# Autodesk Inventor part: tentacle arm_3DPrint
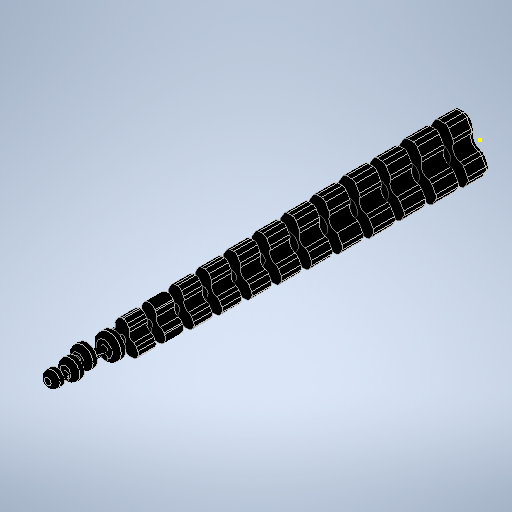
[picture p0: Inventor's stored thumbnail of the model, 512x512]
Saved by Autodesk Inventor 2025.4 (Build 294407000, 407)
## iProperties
Created: 2026-05
Part Number: tentacle arm_3DPrint
Material: Generic
Document SubType Name: Modeling
Designer: PC
Density: 1 g/cm^3
Appearance: Default
Author: PC
Part Number: TENTACLE
Material: ABS Plastic
Density: 1.06 g/cm^3
Appearance: Anodized - Black
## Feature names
1. Extrusion1
2. Fillet1
3. Extrusion2
4. Extrusion3
5. Fillet2
6. Extrusion4
7. Extrusion5
8. Fillet3
9. Extrusion6
10. Extrusion7
11. Fillet4
12. Extrusion8
13. Extrusion9
14. Fillet5
15. Extrusion10
16. Extrusion11
17. Fillet6
18. Extrusion12
19. Extrusion13
20. Fillet7
21. Extrusion14
22. Extrusion15
23. Fillet8
24. Extrusion16
25. Fillet9
26. Extrusion17
27. Fillet10
28. Extrusion18
29. Extrusion19
30. Fillet11
31. Extrusion20
32. Extrusion21
33. Fillet12
34. Extrusion22
35. Extrusion23
36. Fillet13
37. Extrusion24
38. Extrusion25
39. Extrusion26
40. Extrusion27
41. Extrusion28
42. Fillet14
43. Fillet15
44. Fillet16
45. Fillet17
46. Sweep1
47. Sweep2
48. Sweep3
49. Extrusion29
## Parameters: d0 = 4 mm, d1 = 12.5 mm, d2 = 25 mm, d3 = 5 mm, d4 = 6 mm, d5 = 120 deg, d7 = 12.5 mm, d14 = 2.5 mm, d16 = 120 deg, d17 = 2.5 mm, d18 = 5 mm, d19 = 6 mm, d20 = 120 deg, d21 = 6 mm, d22 = 4 mm, d23 = 4 mm, d24 = 4 mm, d32 = 0, d33 = 2 mm, d34 = 4 mm, d35 = 4 mm, d36 = 0, d70 = 3.89 mm, d71 = 12.225 mm, d72 = 24.45 mm, d73 = 4.89 mm, d74 = 5.868 mm, d75 = 120 deg, d76 = 12.225 mm, d77 = 2.445 mm, d78 = 120 deg, d79 = 2.445 mm, d80 = 4.89 mm, d81 = 5.868 mm, d82 = 120 deg, d83 = 5.868 mm, d84 = 3.912 mm, d85 = 3.912 mm, d86 = 3.912 mm, d93 = 0, d94 = 9.8 mm, d95 = 0, d96 = 2 mm, d97 = 4 mm, d98 = 0, d99 = 3.78 mm, d100 = 11.61375 mm, d101 = 23.2275 mm, d102 = 4.6455 mm, d103 = 5.5746 mm, d104 = 120 deg, d105 = 11.61375 mm, d106 = 2.32275 mm, d107 = 120 deg, d108 = 2.32275 mm, d109 = 4.6455 mm, d110 = 5.5746 mm, d111 = 120 deg, d112 = 5.5746 mm, d113 = 3.716 mm, d114 = 3.716 mm, d115 = 3.716 mm, d116 = 2.4 mm, d117 = 15 mm, d122 = 0, d123 = 0, d124 = 0, d125 = 9.6 mm, d126 = 0, d127 = 2 mm, d128 = 4 mm, d129 = 0, d130 = 3.6 mm, d131 = 11.61375 mm, d132 = 23.2275 mm, d133 = 4.6455 mm, d134 = 5.5746 mm, d135 = 120 deg, d136 = 11.61375 mm, d137 = 2.32275 mm, d138 = 120 deg, d139 = 2.32275 mm, d140 = 4.6455 mm, d141 = 5.5746 mm, d142 = 120 deg, d143 = 5.5746 mm, d144 = 3.716 mm, d145 = 3.716 mm, d146 = 3.716 mm, d147 = 2.5 mm, d148 = 15 mm, d153 = 0, d154 = 0, d155 = 0, d156 = 0, d157 = 9.5 mm, d158 = 0, d159 = 2 mm, d160 = 4 mm, d161 = 0, d162 = 3.4 mm, d163 = 11.03306 mm, d164 = 22.06612 mm, d165 = 4.41322 mm, d166 = 5.29587 mm, d167 = 120 deg, d168 = 11.03306 mm, d169 = 2.20661 mm, d170 = 120 deg, d171 = 2.20661 mm, d172 = 4.41323 mm, d173 = 5.29587 mm, d174 = 120 deg, d175 = 5.29587 mm, d176 = 3.53 mm, d177 = 3.53 mm, d178 = 3.53 mm, d179 = 2.5 mm, d180 = 14 mm, d185 = 0 mm, d186 = 0, d187 = 0, d188 = 0 mm, d189 = 0, d190 = 0, d191 = 9.2 mm, d192 = 0, d193 = 2 mm, d194 = 4 mm, d195 = 0, d196 = 3.1 mm, d197 = 10.48141 mm, d198 = 20.96282 mm, d199 = 4.19256 mm, d200 = 5.03108 mm, d201 = 120 deg, d202 = 10.48141 mm, d203 = 2.09628 mm, d204 = 120 deg, d205 = 2.09628 mm, d206 = 4.19256 mm, d207 = 5.03108 mm, d208 = 120 deg, d209 = 5.03108 mm, d210 = 3.354 mm, d211 = 3.354 mm, d212 = 3.354 mm, d219 = 0 deg, d220 = 0, d221 = 0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
